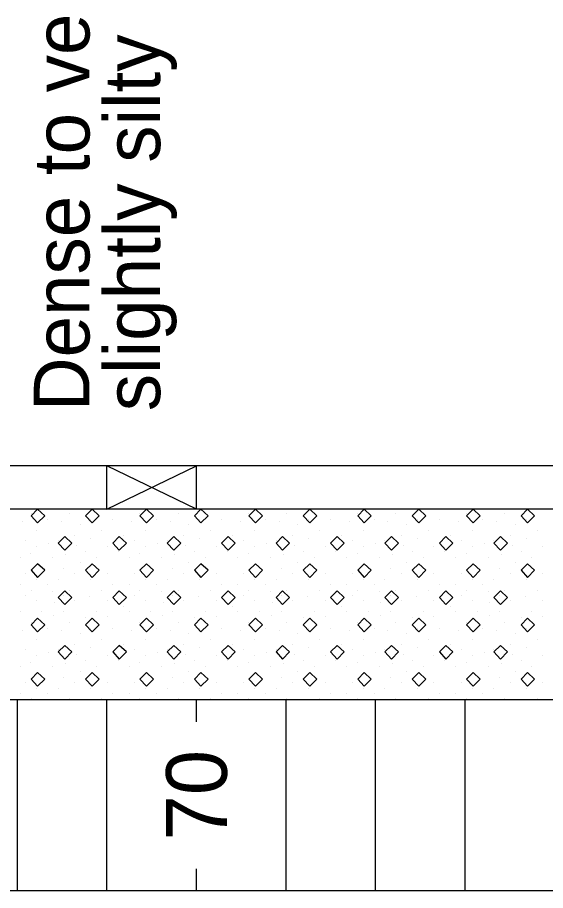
# Model space of a CAD drawing. Extents: x 1313964 to 1316843, y 2087046 to 2096619.
# Drawn here: x 1314112.29 to 1314118.19, y 2089873.43 to 2089883.18 of the extents above; entities that cross this region are included whole.
import ezdxf

# ---------------------------------------------------------------- set-up
doc = ezdxf.new("R2010")
doc.units = 0
doc.layers.add('B-Sub-Contour', color=7, linetype='Continuous')
doc.layers.add('Default', color=7, linetype='Continuous')

# ---------------------------------------------------------------- blocks, each defined once
blk = doc.blocks.new('POINT_DISPLAY')
at = {"layer": 'Default'}
blk.add_line((0, 0), (0, 0), dxfattribs=at)

msp = doc.modelspace()

# ---------------------------------------------------------------- linework, layer by layer
at = {"layer": 'B-Sub-Contour'}
for points in [[(1314136.7248, 2089873.4343), (1314136.7248, 2089916.3058), (1314075.306, 2089916.3058), (1314075.306, 2089873.4343), (1314136.7248, 2089873.4343)], [(1314134.2924, 2089878.1775), (1314089.2925, 2089878.1775)], [(1314113.2924, 2089877.691), (1314114.2924, 2089878.1775)], [(1314114.2924, 2089877.691), (1314113.2924, 2089878.1775)], [(1314113.2924, 2089877.691), (1314113.2924, 2089878.1775)], [(1314114.2924, 2089877.691), (1314114.2924, 2089878.1775)], [(1314134.2924, 2089877.691), (1314082.6033, 2089877.691)], [(1314134.2924, 2089875.5627), (1314082.6033, 2089875.5627)], [(1314112.2924, 2089873.4343), (1314112.2924, 2089875.5627)], [(1314112.2924, 2089873.4343), (1314112.2924, 2089875.5627)], [(1314113.2924, 2089873.4343), (1314113.2924, 2089875.5627)], [(1314114.2924, 2089875.3194), (1314114.2924, 2089875.5627)], [(1314114.2924, 2089875.3194), (1314114.2924, 2089875.5627)], [(1314115.2924, 2089873.4343), (1314115.2924, 2089875.5627)], [(1314116.2924, 2089873.4343), (1314116.2924, 2089875.5627)], [(1314116.2924, 2089873.4343), (1314116.2924, 2089875.5627)], [(1314117.2924, 2089873.4343), (1314117.2924, 2089875.5627)], [(1314114.2924, 2089873.4343), (1314114.2924, 2089873.6775)], [(1314114.2924, 2089873.4343), (1314114.2924, 2089873.6775)]]:
    msp.add_lwpolyline(points, dxfattribs=at)
for points in [[(1314112.5174, 2089877.691), (1314112.4444, 2089877.6181), (1314112.5174, 2089877.539), (1314112.5965, 2089877.6181)], [(1314113.1255, 2089877.691), (1314113.0525, 2089877.6181), (1314113.1255, 2089877.539), (1314113.2046, 2089877.6181)], [(1314113.7336, 2089877.691), (1314113.6607, 2089877.6181), (1314113.7336, 2089877.539), (1314113.8127, 2089877.6181)], [(1314114.3417, 2089877.691), (1314114.2688, 2089877.6181), (1314114.3417, 2089877.539), (1314114.4208, 2089877.6181)], [(1314114.9498, 2089877.691), (1314114.8769, 2089877.6181), (1314114.9498, 2089877.539), (1314115.0289, 2089877.6181)], [(1314115.5579, 2089877.691), (1314115.485, 2089877.6181), (1314115.5579, 2089877.539), (1314115.637, 2089877.6181)], [(1314116.1661, 2089877.691), (1314116.0931, 2089877.6181), (1314116.1661, 2089877.539), (1314116.2451, 2089877.6181)], [(1314116.7742, 2089877.691), (1314116.7012, 2089877.6181), (1314116.7742, 2089877.539), (1314116.8532, 2089877.6181)], [(1314117.3823, 2089877.691), (1314117.3093, 2089877.6181), (1314117.3823, 2089877.539), (1314117.4613, 2089877.6181)], [(1314117.9904, 2089877.691), (1314117.9174, 2089877.6181), (1314117.9904, 2089877.539), (1314118.0694, 2089877.6181)], [(1314112.8215, 2089877.387), (1314112.7485, 2089877.314), (1314112.8215, 2089877.235), (1314112.9005, 2089877.314)], [(1314113.4296, 2089877.387), (1314113.3566, 2089877.314), (1314113.4296, 2089877.235), (1314113.5086, 2089877.314)], [(1314114.0377, 2089877.387), (1314113.9647, 2089877.314), (1314114.0377, 2089877.235), (1314114.1167, 2089877.314)], [(1314114.6458, 2089877.387), (1314114.5728, 2089877.314), (1314114.6458, 2089877.235), (1314114.7248, 2089877.314)], [(1314115.2539, 2089877.387), (1314115.1809, 2089877.314), (1314115.2539, 2089877.235), (1314115.3329, 2089877.314)], [(1314115.862, 2089877.387), (1314115.789, 2089877.314), (1314115.862, 2089877.235), (1314115.9411, 2089877.314)], [(1314116.4701, 2089877.387), (1314116.3971, 2089877.314), (1314116.4701, 2089877.235), (1314116.5492, 2089877.314)], [(1314117.0782, 2089877.387), (1314117.0052, 2089877.314), (1314117.0782, 2089877.235), (1314117.1573, 2089877.314)], [(1314117.6863, 2089877.387), (1314117.6133, 2089877.314), (1314117.6863, 2089877.235), (1314117.7654, 2089877.314)], [(1314112.5174, 2089877.0829), (1314112.4444, 2089877.01), (1314112.5174, 2089876.9309), (1314112.5965, 2089877.01)], [(1314113.1255, 2089877.0829), (1314113.0525, 2089877.01), (1314113.1255, 2089876.9309), (1314113.2046, 2089877.01)], [(1314113.7336, 2089877.0829), (1314113.6607, 2089877.01), (1314113.7336, 2089876.9309), (1314113.8127, 2089877.01)], [(1314114.3417, 2089877.0829), (1314114.2688, 2089877.01), (1314114.3417, 2089876.9309), (1314114.4208, 2089877.01)], [(1314114.9498, 2089877.0829), (1314114.8769, 2089877.01), (1314114.9498, 2089876.9309), (1314115.0289, 2089877.01)], [(1314115.5579, 2089877.0829), (1314115.485, 2089877.01), (1314115.5579, 2089876.9309), (1314115.637, 2089877.01)], [(1314116.1661, 2089877.0829), (1314116.0931, 2089877.01), (1314116.1661, 2089876.9309), (1314116.2451, 2089877.01)], [(1314116.7742, 2089877.0829), (1314116.7012, 2089877.01), (1314116.7742, 2089876.9309), (1314116.8532, 2089877.01)], [(1314117.3823, 2089877.0829), (1314117.3093, 2089877.01), (1314117.3823, 2089876.9309), (1314117.4613, 2089877.01)], [(1314117.9904, 2089877.0829), (1314117.9174, 2089877.01), (1314117.9904, 2089876.9309), (1314118.0694, 2089877.01)], [(1314112.8215, 2089876.7789), (1314112.7485, 2089876.7059), (1314112.8215, 2089876.6268), (1314112.9005, 2089876.7059)], [(1314113.4296, 2089876.7789), (1314113.3566, 2089876.7059), (1314113.4296, 2089876.6268), (1314113.5086, 2089876.7059)], [(1314114.0377, 2089876.7789), (1314113.9647, 2089876.7059), (1314114.0377, 2089876.6268), (1314114.1167, 2089876.7059)], [(1314114.6458, 2089876.7789), (1314114.5728, 2089876.7059), (1314114.6458, 2089876.6268), (1314114.7248, 2089876.7059)], [(1314115.2539, 2089876.7789), (1314115.1809, 2089876.7059), (1314115.2539, 2089876.6268), (1314115.3329, 2089876.7059)], [(1314115.862, 2089876.7789), (1314115.789, 2089876.7059), (1314115.862, 2089876.6268), (1314115.9411, 2089876.7059)], [(1314116.4701, 2089876.7789), (1314116.3971, 2089876.7059), (1314116.4701, 2089876.6268), (1314116.5492, 2089876.7059)], [(1314117.0782, 2089876.7789), (1314117.0052, 2089876.7059), (1314117.0782, 2089876.6268), (1314117.1573, 2089876.7059)], [(1314117.6863, 2089876.7789), (1314117.6133, 2089876.7059), (1314117.6863, 2089876.6268), (1314117.7654, 2089876.7059)], [(1314112.5174, 2089876.4748), (1314112.4444, 2089876.4018), (1314112.5174, 2089876.3228), (1314112.5965, 2089876.4018)], [(1314113.1255, 2089876.4748), (1314113.0525, 2089876.4018), (1314113.1255, 2089876.3228), (1314113.2046, 2089876.4018)], [(1314113.7336, 2089876.4748), (1314113.6607, 2089876.4018), (1314113.7336, 2089876.3228), (1314113.8127, 2089876.4018)], [(1314114.3417, 2089876.4748), (1314114.2688, 2089876.4018), (1314114.3417, 2089876.3228), (1314114.4208, 2089876.4018)], [(1314114.9498, 2089876.4748), (1314114.8769, 2089876.4018), (1314114.9498, 2089876.3228), (1314115.0289, 2089876.4018)], [(1314115.5579, 2089876.4748), (1314115.485, 2089876.4018), (1314115.5579, 2089876.3228), (1314115.637, 2089876.4018)], [(1314116.1661, 2089876.4748), (1314116.0931, 2089876.4018), (1314116.1661, 2089876.3228), (1314116.2451, 2089876.4018)], [(1314116.7742, 2089876.4748), (1314116.7012, 2089876.4018), (1314116.7742, 2089876.3228), (1314116.8532, 2089876.4018)], [(1314117.3823, 2089876.4748), (1314117.3093, 2089876.4018), (1314117.3823, 2089876.3228), (1314117.4613, 2089876.4018)], [(1314117.9904, 2089876.4748), (1314117.9174, 2089876.4018), (1314117.9904, 2089876.3228), (1314118.0694, 2089876.4018)], [(1314112.8215, 2089876.1708), (1314112.7485, 2089876.0978), (1314112.8215, 2089876.0187), (1314112.9005, 2089876.0978)], [(1314113.4296, 2089876.1708), (1314113.3566, 2089876.0978), (1314113.4296, 2089876.0187), (1314113.5086, 2089876.0978)], [(1314114.0377, 2089876.1708), (1314113.9647, 2089876.0978), (1314114.0377, 2089876.0187), (1314114.1167, 2089876.0978)], [(1314114.6458, 2089876.1708), (1314114.5728, 2089876.0978), (1314114.6458, 2089876.0187), (1314114.7248, 2089876.0978)], [(1314115.2539, 2089876.1708), (1314115.1809, 2089876.0978), (1314115.2539, 2089876.0187), (1314115.3329, 2089876.0978)], [(1314115.862, 2089876.1708), (1314115.789, 2089876.0978), (1314115.862, 2089876.0187), (1314115.9411, 2089876.0978)], [(1314116.4701, 2089876.1708), (1314116.3971, 2089876.0978), (1314116.4701, 2089876.0187), (1314116.5492, 2089876.0978)], [(1314117.0782, 2089876.1708), (1314117.0052, 2089876.0978), (1314117.0782, 2089876.0187), (1314117.1573, 2089876.0978)], [(1314117.6863, 2089876.1708), (1314117.6133, 2089876.0978), (1314117.6863, 2089876.0187), (1314117.7654, 2089876.0978)], [(1314112.5174, 2089875.8667), (1314112.4444, 2089875.7937), (1314112.5174, 2089875.7147), (1314112.5965, 2089875.7937)], [(1314113.1255, 2089875.8667), (1314113.0525, 2089875.7937), (1314113.1255, 2089875.7147), (1314113.2046, 2089875.7937)], [(1314113.7336, 2089875.8667), (1314113.6607, 2089875.7937), (1314113.7336, 2089875.7147), (1314113.8127, 2089875.7937)], [(1314114.3417, 2089875.8667), (1314114.2688, 2089875.7937), (1314114.3417, 2089875.7147), (1314114.4208, 2089875.7937)], [(1314114.9498, 2089875.8667), (1314114.8769, 2089875.7937), (1314114.9498, 2089875.7147), (1314115.0289, 2089875.7937)], [(1314115.5579, 2089875.8667), (1314115.485, 2089875.7937), (1314115.5579, 2089875.7147), (1314115.637, 2089875.7937)], [(1314116.1661, 2089875.8667), (1314116.0931, 2089875.7937), (1314116.1661, 2089875.7147), (1314116.2451, 2089875.7937)], [(1314116.7742, 2089875.8667), (1314116.7012, 2089875.7937), (1314116.7742, 2089875.7147), (1314116.8532, 2089875.7937)], [(1314117.3823, 2089875.8667), (1314117.3093, 2089875.7937), (1314117.3823, 2089875.7147), (1314117.4613, 2089875.7937)], [(1314117.9904, 2089875.8667), (1314117.9174, 2089875.7937), (1314117.9904, 2089875.7147), (1314118.0694, 2089875.7937)]]:
    msp.add_lwpolyline(points, close=True, dxfattribs=at)

# ---------------------------------------------------------------- block references
at = {"layer": 'B-Sub-Contour', "xscale": 0.019951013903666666, "yscale": 0.019951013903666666, "rotation": 90}
for p in [(1314112.4444, 2089877.6409), (1314112.8701, 2089877.6409), (1314113.6607, 2089877.6409), (1314114.0863, 2089877.6409), (1314114.8769, 2089877.6409), (1314115.3025, 2089877.6409), (1314116.0931, 2089877.6409), (1314116.5188, 2089877.6409), (1314117.3093, 2089877.6409), (1314117.735, 2089877.6409), (1314112.3532, 2089877.5551), (1314112.6269, 2089877.5801), (1314112.7817, 2089877.5524), (1314113.1134, 2089877.5801), (1314113.3566, 2089877.5801), (1314113.5694, 2089877.5551), (1314113.8431, 2089877.5801), (1314113.9979, 2089877.5524), (1314114.3296, 2089877.5801), (1314114.5728, 2089877.5801), (1314114.7856, 2089877.5551), (1314115.0593, 2089877.5801), (1314115.2141, 2089877.5524), (1314115.5458, 2089877.5801), (1314115.789, 2089877.5801), (1314116.0019, 2089877.5551), (1314116.2755, 2089877.5801), (1314116.4303, 2089877.5524), (1314116.762, 2089877.5801), (1314117.0052, 2089877.5801), (1314117.2181, 2089877.5551), (1314117.4917, 2089877.5801), (1314117.6465, 2089877.5524), (1314117.9782, 2089877.5801), (1314112.5052, 2089877.4584), (1314112.9917, 2089877.5192), (1314113.235, 2089877.4584), (1314113.7215, 2089877.4584), (1314114.2079, 2089877.5192), (1314114.4512, 2089877.4584), (1314114.9377, 2089877.4584), (1314115.4242, 2089877.5192), (1314115.6674, 2089877.4584), (1314116.1539, 2089877.4584), (1314116.6404, 2089877.5192), (1314116.8836, 2089877.4584), (1314117.3701, 2089877.4584), (1314117.8566, 2089877.5192), (1314118.0998, 2089877.4584), (1314112.9309, 2089877.3976), (1314113.1134, 2089877.3592), (1314113.4782, 2089877.3976), (1314114.1471, 2089877.3976), (1314114.3296, 2089877.3592), (1314114.6944, 2089877.3976), (1314115.3634, 2089877.3976), (1314115.5458, 2089877.3592), (1314115.9106, 2089877.3976), (1314116.5796, 2089877.3976), (1314116.762, 2089877.3592), (1314117.1269, 2089877.3976), (1314117.7958, 2089877.3976), (1314117.9782, 2089877.3592), (1314112.3836, 2089877.3368), (1314112.5052, 2089877.276), (1314112.6435, 2089877.3067), (1314112.7485, 2089877.3368), (1314112.9558, 2089877.2818), (1314113.2958, 2089877.276), (1314113.5998, 2089877.3368), (1314113.7215, 2089877.276), (1314113.8597, 2089877.3067), (1314113.9647, 2089877.3368), (1314114.172, 2089877.2818), (1314114.512, 2089877.276), (1314114.8161, 2089877.3368), (1314114.9377, 2089877.276), (1314115.0759, 2089877.3067), (1314115.1809, 2089877.3368), (1314115.3882, 2089877.2818), (1314115.7282, 2089877.276), (1314116.0323, 2089877.3368), (1314116.1539, 2089877.276), (1314116.2921, 2089877.3067), (1314116.3971, 2089877.3368), (1314116.6044, 2089877.2818), (1314116.9444, 2089877.276), (1314117.2485, 2089877.3368), (1314117.3701, 2089877.276), (1314117.5083, 2089877.3067), (1314117.6133, 2089877.3368), (1314117.8207, 2089877.2818), (1314118.1606, 2089877.276), (1314112.3228, 2089877.1544), (1314112.4389, 2089877.1962), (1314112.6877, 2089877.1544), (1314112.8287, 2089877.1879), (1314113.0525, 2089877.2152), (1314113.1742, 2089877.1544), (1314113.4174, 2089877.2152), (1314113.539, 2089877.1544), (1314113.6551, 2089877.1962), (1314113.9039, 2089877.1544), (1314114.0449, 2089877.1879), (1314114.2688, 2089877.2152), (1314114.3904, 2089877.1544), (1314114.6336, 2089877.2152), (1314114.7552, 2089877.1544), (1314114.8713, 2089877.1962), (1314115.1201, 2089877.1544), (1314115.2611, 2089877.1879), (1314115.485, 2089877.2152), (1314115.6066, 2089877.1544), (1314115.8498, 2089877.2152), (1314115.9715, 2089877.1544), (1314116.0876, 2089877.1962), (1314116.3363, 2089877.1544), (1314116.4773, 2089877.1879), (1314116.7012, 2089877.2152), (1314116.8228, 2089877.1544), (1314117.066, 2089877.2152), (1314117.1877, 2089877.1544), (1314117.3038, 2089877.1962), (1314117.5525, 2089877.1544), (1314117.6935, 2089877.1879), (1314117.9174, 2089877.2152), (1314118.039, 2089877.1544), (1314112.9917, 2089877.0936), (1314114.2079, 2089877.0936), (1314115.4242, 2089877.0936), (1314116.6404, 2089877.0936), (1314117.8566, 2089877.0936), (1314112.3836, 2089876.9719), (1314112.5661, 2089877.0328), (1314112.8093, 2089877.0328), (1314112.9309, 2089876.9719), (1314113.2958, 2089876.9719), (1314113.5998, 2089876.9719), (1314113.7823, 2089877.0328), (1314114.0255, 2089877.0328), (1314114.1471, 2089876.9719), (1314114.512, 2089876.9719), (1314114.8161, 2089876.9719), (1314114.9985, 2089877.0328), (1314115.2417, 2089877.0328), (1314115.3634, 2089876.9719), (1314115.7282, 2089876.9719), (1314116.0323, 2089876.9719), (1314116.2147, 2089877.0328), (1314116.4579, 2089877.0328), (1314116.5796, 2089876.9719), (1314116.9444, 2089876.9719), (1314117.2485, 2089876.9719), (1314117.4309, 2089877.0328), (1314117.6742, 2089877.0328), (1314117.7958, 2089876.9719), (1314118.1606, 2089876.9719), (1314112.3228, 2089876.8503), (1314112.5052, 2089876.9111), (1314112.6269, 2089876.8503), (1314112.7485, 2089876.9111), (1314113.1134, 2089876.9111), (1314113.3566, 2089876.8503), (1314113.539, 2089876.8503), (1314113.7215, 2089876.9111), (1314113.8431, 2089876.8503), (1314113.9647, 2089876.9111), (1314114.3296, 2089876.9111), (1314114.5728, 2089876.8503), (1314114.7552, 2089876.8503), (1314114.9377, 2089876.9111), (1314115.0593, 2089876.8503), (1314115.1809, 2089876.9111), (1314115.5458, 2089876.9111), (1314115.789, 2089876.8503), (1314115.9715, 2089876.8503), (1314116.1539, 2089876.9111), (1314116.2755, 2089876.8503), (1314116.3971, 2089876.9111), (1314116.762, 2089876.9111), (1314117.0052, 2089876.8503), (1314117.1877, 2089876.8503), (1314117.3701, 2089876.9111), (1314117.4917, 2089876.8503), (1314117.6133, 2089876.9111), (1314117.9782, 2089876.9111), (1314112.4444, 2089876.7895), (1314112.6877, 2089876.7682), (1314112.8701, 2089876.7895), (1314113.235, 2089876.7895), (1314113.4174, 2089876.7758), (1314113.6607, 2089876.7895), (1314113.9039, 2089876.7682), (1314114.0863, 2089876.7895), (1314114.4512, 2089876.7895), (1314114.6336, 2089876.7758), (1314114.8769, 2089876.7895), (1314115.1201, 2089876.7682), (1314115.3025, 2089876.7895), (1314115.6674, 2089876.7895), (1314115.8498, 2089876.7758), (1314116.0931, 2089876.7895), (1314116.3363, 2089876.7682), (1314116.5188, 2089876.7895), (1314116.8836, 2089876.7895), (1314117.066, 2089876.7758), (1314117.3093, 2089876.7895), (1314117.5525, 2089876.7682), (1314117.735, 2089876.7895), (1314118.0998, 2089876.7895), (1314112.3836, 2089876.7287), (1314112.5052, 2089876.6679), (1314112.8093, 2089876.7287), (1314112.9309, 2089876.6679), (1314113.0995, 2089876.7119), (1314113.2958, 2089876.6679), (1314113.5998, 2089876.7287), (1314113.7215, 2089876.6679), (1314114.0255, 2089876.7287), (1314114.1471, 2089876.6679), (1314114.3157, 2089876.7119), (1314114.512, 2089876.6679), (1314114.8161, 2089876.7287), (1314114.9377, 2089876.6679), (1314115.2417, 2089876.7287), (1314115.3634, 2089876.6679), (1314115.532, 2089876.7119), (1314115.7282, 2089876.6679), (1314116.0323, 2089876.7287), (1314116.1539, 2089876.6679), (1314116.4579, 2089876.7287), (1314116.5796, 2089876.6679), (1314116.7482, 2089876.7119), (1314116.9444, 2089876.6679), (1314117.2485, 2089876.7287), (1314117.3701, 2089876.6679), (1314117.6742, 2089876.7287), (1314117.7958, 2089876.6679), (1314117.9644, 2089876.7119), (1314118.1606, 2089876.6679), (1314112.7043, 2089876.6483), (1314113.4782, 2089876.6071), (1314113.9205, 2089876.6483), (1314114.6944, 2089876.6071), (1314115.1367, 2089876.6483), (1314115.9106, 2089876.6071), (1314116.3529, 2089876.6483), (1314117.1269, 2089876.6071), (1314117.5691, 2089876.6483), (1314112.3228, 2089876.5463), (1314112.5661, 2089876.5463), (1314112.696, 2089876.5019), (1314112.8093, 2089876.5463), (1314113.0525, 2089876.4855), (1314113.1742, 2089876.5463), (1314113.2958, 2089876.4882), (1314113.539, 2089876.5463), (1314113.7823, 2089876.5463), (1314113.9122, 2089876.5019), (1314114.0255, 2089876.5463), (1314114.2688, 2089876.4855), (1314114.3904, 2089876.5463), (1314114.512, 2089876.4882), (1314114.7552, 2089876.5463), (1314114.9985, 2089876.5463), (1314115.1284, 2089876.5019), (1314115.2417, 2089876.5463), (1314115.485, 2089876.4855), (1314115.6066, 2089876.5463), (1314115.7282, 2089876.4882), (1314115.9715, 2089876.5463), (1314116.2147, 2089876.5463), (1314116.3446, 2089876.5019), (1314116.4579, 2089876.5463), (1314116.7012, 2089876.4855), (1314116.8228, 2089876.5463), (1314116.9444, 2089876.4882), (1314117.1877, 2089876.5463), (1314117.4309, 2089876.5463), (1314117.5608, 2089876.5019), (1314117.6742, 2089876.5463), (1314117.9174, 2089876.4855), (1314118.039, 2089876.5463), (1314118.1606, 2089876.4882), (1314112.4444, 2089876.4246), (1314112.6269, 2089876.3638), (1314112.8701, 2089876.4246), (1314113.1134, 2089876.3638), (1314113.3566, 2089876.3638), (1314113.6607, 2089876.4246), (1314113.8431, 2089876.3638), (1314114.0863, 2089876.4246), (1314114.3296, 2089876.3638), (1314114.5728, 2089876.3638), (1314114.8769, 2089876.4246), (1314115.0593, 2089876.3638), (1314115.3025, 2089876.4246), (1314115.5458, 2089876.3638), (1314115.789, 2089876.3638), (1314116.0931, 2089876.4246), (1314116.2755, 2089876.3638), (1314116.5188, 2089876.4246), (1314116.762, 2089876.3638), (1314117.0052, 2089876.3638), (1314117.3093, 2089876.4246), (1314117.4917, 2089876.3638), (1314117.735, 2089876.4246), (1314117.9782, 2089876.3638), (1314112.3532, 2089876.3389), (1314112.7817, 2089876.3362), (1314112.9917, 2089876.303), (1314113.5694, 2089876.3389), (1314113.9979, 2089876.3362), (1314114.2079, 2089876.303), (1314114.7856, 2089876.3389), (1314115.2141, 2089876.3362), (1314115.4242, 2089876.303), (1314116.0019, 2089876.3389), (1314116.4303, 2089876.3362), (1314116.6404, 2089876.303), (1314117.2181, 2089876.3389), (1314117.6465, 2089876.3362), (1314117.8566, 2089876.303), (1314112.5052, 2089876.2422), (1314112.9309, 2089876.1814), (1314113.235, 2089876.2422), (1314113.4782, 2089876.1814), (1314113.7215, 2089876.2422), (1314114.1471, 2089876.1814), (1314114.4512, 2089876.2422), (1314114.6944, 2089876.1814), (1314114.9377, 2089876.2422), (1314115.3634, 2089876.1814), (1314115.6674, 2089876.2422), (1314115.9106, 2089876.1814), (1314116.1539, 2089876.2422), (1314116.5796, 2089876.1814), (1314116.8836, 2089876.2422), (1314117.1269, 2089876.1814), (1314117.3701, 2089876.2422), (1314117.7958, 2089876.1814), (1314118.0998, 2089876.2422), (1314112.3836, 2089876.1206), (1314112.6435, 2089876.0905), (1314112.7485, 2089876.1206), (1314113.1134, 2089876.143), (1314113.5998, 2089876.1206), (1314113.8597, 2089876.0905), (1314113.9647, 2089876.1206), (1314114.3296, 2089876.143), (1314114.8161, 2089876.1206), (1314115.0759, 2089876.0905), (1314115.1809, 2089876.1206), (1314115.5458, 2089876.143), (1314116.0323, 2089876.1206), (1314116.2921, 2089876.0905), (1314116.3971, 2089876.1206), (1314116.762, 2089876.143), (1314117.2485, 2089876.1206), (1314117.5083, 2089876.0905), (1314117.6133, 2089876.1206), (1314117.9782, 2089876.143), (1314112.4389, 2089875.98), (1314112.5052, 2089876.0598), (1314112.9558, 2089876.0656), (1314113.0525, 2089875.999), (1314113.2958, 2089876.0598), (1314113.4174, 2089875.999), (1314113.6551, 2089875.98), (1314113.7215, 2089876.0598), (1314114.172, 2089876.0656), (1314114.2688, 2089875.999), (1314114.512, 2089876.0598), (1314114.6336, 2089875.999), (1314114.8713, 2089875.98), (1314114.9377, 2089876.0598), (1314115.3882, 2089876.0656), (1314115.485, 2089875.999), (1314115.7282, 2089876.0598), (1314115.8498, 2089875.999), (1314116.0876, 2089875.98), (1314116.1539, 2089876.0598), (1314116.6044, 2089876.0656), (1314116.7012, 2089875.999), (1314116.9444, 2089876.0598), (1314117.066, 2089875.999), (1314117.3038, 2089875.98), (1314117.3701, 2089876.0598), (1314117.8207, 2089876.0656), (1314117.9174, 2089875.999), (1314118.1606, 2089876.0598), (1314112.3228, 2089875.9382), (1314112.6877, 2089875.9382), (1314112.8287, 2089875.9717), (1314112.9917, 2089875.8774), (1314113.1742, 2089875.9382), (1314113.539, 2089875.9382), (1314113.9039, 2089875.9382), (1314114.0449, 2089875.9717), (1314114.2079, 2089875.8774), (1314114.3904, 2089875.9382), (1314114.7552, 2089875.9382), (1314115.1201, 2089875.9382), (1314115.2611, 2089875.9717), (1314115.4242, 2089875.8774), (1314115.6066, 2089875.9382), (1314115.9715, 2089875.9382), (1314116.3363, 2089875.9382), (1314116.4773, 2089875.9717), (1314116.6404, 2089875.8774), (1314116.8228, 2089875.9382), (1314117.1877, 2089875.9382), (1314117.5525, 2089875.9382), (1314117.6935, 2089875.9717), (1314117.8566, 2089875.8774), (1314118.039, 2089875.9382), (1314112.5661, 2089875.8165), (1314112.8093, 2089875.8165), (1314113.7823, 2089875.8165), (1314114.0255, 2089875.8165), (1314114.9985, 2089875.8165), (1314115.2417, 2089875.8165), (1314116.2147, 2089875.8165), (1314116.4579, 2089875.8165), (1314117.4309, 2089875.8165), (1314117.6742, 2089875.8165), (1314112.3836, 2089875.7557), (1314112.5052, 2089875.6949), (1314112.7485, 2089875.6949), (1314112.9309, 2089875.7557), (1314113.1134, 2089875.6949), (1314113.2958, 2089875.7557), (1314113.5998, 2089875.7557), (1314113.7215, 2089875.6949), (1314113.9647, 2089875.6949), (1314114.1471, 2089875.7557), (1314114.3296, 2089875.6949), (1314114.512, 2089875.7557), (1314114.8161, 2089875.7557), (1314114.9377, 2089875.6949), (1314115.1809, 2089875.6949), (1314115.3634, 2089875.7557), (1314115.5458, 2089875.6949), (1314115.7282, 2089875.7557), (1314116.0323, 2089875.7557), (1314116.1539, 2089875.6949), (1314116.3971, 2089875.6949), (1314116.5796, 2089875.7557), (1314116.762, 2089875.6949), (1314116.9444, 2089875.7557), (1314117.2485, 2089875.7557), (1314117.3701, 2089875.6949), (1314117.6133, 2089875.6949), (1314117.7958, 2089875.7557), (1314117.9782, 2089875.6949), (1314118.1606, 2089875.7557), (1314112.3228, 2089875.6341), (1314112.6269, 2089875.6341), (1314113.3566, 2089875.6341), (1314113.539, 2089875.6341), (1314113.8431, 2089875.6341), (1314114.5728, 2089875.6341), (1314114.7552, 2089875.6341), (1314115.0593, 2089875.6341), (1314115.789, 2089875.6341), (1314115.9715, 2089875.6341), (1314116.2755, 2089875.6341), (1314117.0052, 2089875.6341), (1314117.1877, 2089875.6341), (1314117.4917, 2089875.6341), (1314112.4444, 2089875.5733), (1314112.8701, 2089875.5733), (1314113.235, 2089875.5733), (1314113.6607, 2089875.5733), (1314114.0863, 2089875.5733), (1314114.4512, 2089875.5733), (1314114.8769, 2089875.5733), (1314115.3025, 2089875.5733), (1314115.6674, 2089875.5733), (1314116.0931, 2089875.5733), (1314116.5188, 2089875.5733), (1314116.8836, 2089875.5733), (1314117.3093, 2089875.5733), (1314117.735, 2089875.5733), (1314118.0998, 2089875.5733)]:
    msp.add_blockref('POINT_DISPLAY', p, dxfattribs=at)

# ---------------------------------------------------------------- texts
at = {"layer": 'B-Sub-Contour'}
for s, height, p in [('Dense to very dense fine sand,', 0.622093, (1314113.0969, 2089878.7856)), ('slightly silty', 0.622093, (1314113.8863, 2089878.7856)), ('70', 0.67865, (1314114.6317, 2089873.9943)), ('70', 0.67865, (1314114.6317, 2089873.9943))]:
    msp.add_text(s, height=height, rotation=90, dxfattribs=at).set_placement(p)

doc.saveas('drawing.dxf')
